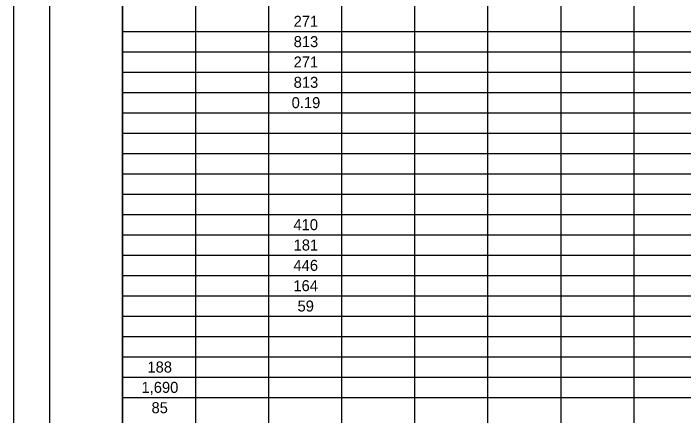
# Model space of a CAD drawing. Extents: x -98 to 34, y 0 to 58.
# Drawn here: x 0 to 9.22, y 10.89 to 16.43 of the extents above; entities that cross this region are included whole.
import ezdxf

# ---------------------------------------------------------------- set-up
doc = ezdxf.new("R2010")
doc.units = 0
for name, color, linetype in [('Default', 7, 'Continuous'), ('SH_Border', 7, 'Continuous'), ('SH_Cut_Line', 7, 'Continuous')]:
    doc.layers.add(name, color=color, linetype=linetype)

msp = doc.modelspace()

# ---------------------------------------------------------------- linework, layer by layer
at = {"layer": 'Default'}
for p, q in [((1.5, 21.5), (1.5, 0.5024)), ((2.5046, 20.9401), (2.5046, 0.5024)), ((3.5092, 20.9401), (3.5092, 0.5024)), ((4.5138, 20.9401), (4.5138, 0.5024)), ((5.5184, 20.9401), (5.5184, 0.5024)), ((6.5229, 20.9401), (6.5229, 0.5024)), ((7.5275, 20.9401), (7.5275, 0.5024)), ((8.5321, 20.9401), (8.5321, 0.5024)), ((1.5, 16.1806), (32, 16.1806)), ((1.5, 15.9006), (32, 15.9006)), ((1.5, 15.6207), (32, 15.6207)), ((1.5, 15.3407), (32, 15.3407)), ((1.5, 15.0607), (32, 15.0607)), ((1.5, 14.7808), (32, 14.7808)), ((1.5, 14.5008), (32, 14.5008)), ((1.5, 14.2208), (32, 14.2208)), ((1.5, 13.9409), (32, 13.9409)), ((1.5, 13.6609), (32, 13.6609)), ((1.5, 13.3809), (32, 13.3809)), ((1.5, 13.101), (32, 13.101)), ((1.5, 12.821), (32, 12.821)), ((1.5, 12.541), (32, 12.541)), ((1.5, 12.2611), (32, 12.2611)), ((1.5, 11.9811), (32, 11.9811)), ((1.5, 11.7011), (32, 11.7011)), ((1.5, 11.4212), (32, 11.4212)), ((1.5, 11.1412), (32, 11.1412))]:
    msp.add_line(p, q, dxfattribs=at)
at = {"layer": 'SH_Border'}
for points in [[(0.5, 21.5), (1.5, 21.5), (1.5, 0.5), (0.5, 0.5)], [(1.5, 21.5), (33.5, 21.5), (33.5, 0.5), (1.5, 0.5)]]:
    msp.add_lwpolyline(points, close=True, dxfattribs=at)
at = {"layer": 'SH_Cut_Line'}
msp.add_lwpolyline([(0, 0), (34, 0), (34, 22), (0, 22)], close=True, dxfattribs=at)

# ---------------------------------------------------------------- texts
at = {"layer": 'Default'}
for s, p in [('271', (3.8541, 16.2448)), ('813', (3.8548, 15.9649)), ('271', (3.8541, 15.6849)), ('813', (3.8548, 15.4049)), ('0.19', (3.8265, 15.125)), ('410', (3.8519, 13.4452)), ('181', (3.8541, 13.1652)), ('446', (3.8525, 12.8852)), ('164', (3.8513, 12.6053)), ('59', (3.9081, 12.3253)), ('188', (1.8435, 11.4854)), ('1,690', (1.7615, 11.2054)), ('85', (1.8997, 10.9255))]:
    msp.add_text(s, height=0.15151, dxfattribs=at).set_placement(p)

doc.saveas('drawing.dxf')
